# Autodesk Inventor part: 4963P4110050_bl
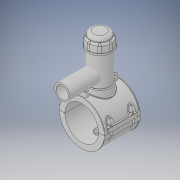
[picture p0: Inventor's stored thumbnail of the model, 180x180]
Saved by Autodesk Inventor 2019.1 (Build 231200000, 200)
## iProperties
Created: 2017-07
Part Number: 4963P4110050_bl
Material: Generic
Document SubType Name: Modeling
Designer: KIM
Density: 1 g/cm^3
Appearance: Default
Author: KIM
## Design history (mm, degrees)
derived "4963P4.ipt"
feature "Solid1::4963P4.ipt" dims "ScaleForDerivedMember" = 10
feature "Solid2::4963P4.ipt" dims "ScaleForDerivedMember" = 10
feature "Solid3::4963P4.ipt" dims "ScaleForDerivedMember" = 10
tag "TaggingFeature1"
body "Solid1"
body "Solid2"
body "Solid3"
other parameters: "d2" = 148 [user parameter], "d3" = 27.5 [user parameter], "d4" = 118 [user parameter], "d5" = 0 [user parameter], "d6" = 0.1 [user parameter], "d8" = 0 [user parameter], "d19" = 6 [user parameter], "d20" = 6 [user parameter], "d21" = 70.8 [user parameter], "d23" = 0 [user parameter], "d24" = 35.4 [user parameter], "d26" = 0 [user parameter], "d27" = 3 [user parameter], "d28" = 3 [user parameter], "d29" = 3 [user parameter], "d30" = 36.66667 [user parameter], "d31" = 6 [user parameter], "d32" = 0 [user parameter], "d33" = 0 [user parameter], "d34" = 0.6 [user parameter], "d40" = 74.36 [user parameter], "d41" = 77 [user parameter], "d43" = 0 [user parameter], "d45" = 0 [user parameter], "d47" = 142.3 [user parameter], "d70" = 15 [user parameter], "d72" = 0 [user parameter], "d73" = 6 [user parameter], "d75" = 5 [user parameter], "d76" = 0 [user parameter], "d77" = 5.5 [user parameter], "d78" = 85 [user parameter], "d79" = 15 [user parameter], "d80" = 47.2 [user parameter], "d82" = 5 deg [user parameter], "d84" = 4 [user parameter], "d85" = 14 [user parameter], "d86" = 0 [user parameter], "d87" = 3 [user parameter], "d88" = 0 [user parameter], "d89" = 1 [user parameter], "d90" = 1 [user parameter], "d91" = 94.4 [user parameter], "d92" = 0 [user parameter], "d93" = 0.5 [user parameter], "d94" = 57.89474 [user parameter], "d96" = 145.86 [user parameter], "d97" = 2.36 [user parameter], "d98" = 0 [user parameter], "d102" = 1.1 [user parameter], "d120" = 140 deg [user parameter], "d121" = 24.228 [user parameter], "d122" = 20 deg [user parameter], "d123" = 286 [user parameter], "d124" = 85.8 [user parameter], "d126" = 0 [user parameter], "d143" = 113.3 [user parameter], "d145" = 25.38462 [user parameter], "d149" = 1.65 [user parameter], "d150" = 27.92308 [user parameter], "d153" = 118 [user parameter], "d154" = 0 [user parameter], "d156" = 71.5 [user parameter], "d157" = 160 deg [user parameter], "d159" = 6.6 [user parameter], "d161" = 1.65 [user parameter], "d162" = 70.8 [user parameter], "d163" = 0 [user parameter], "d164" = 55 [user parameter], "d167" = 11 [user parameter], "d168" = 69.7561 [user parameter], "d170" = 3.75 [user parameter], "d172" = 0 [user parameter], "d173" = 1 [user parameter], "d175" = 55 [user parameter], "d176" = 20 deg [user parameter], "d177" = 7.7 [user parameter], "d178" = 33 [user parameter], "d180" = 0 [user parameter], "d183" = 13.2 [user parameter], "d184" = 6.16 [user parameter], "d185" = 38.35 [user parameter], "d186" = 38.35 [user parameter], "d187" = 71.5 [user parameter], "d188" = 9.9 [user parameter], "d189" = 7.7 [user parameter], "d190" = 0 [user parameter], "d191" = 107.25 [user parameter], "d193" = 8 [user parameter], "d194" = 4.13 [user parameter], "d195" = 90 deg [user parameter], "d197" = 0 [user parameter], "d199" = 0 [user parameter], "d200" = 16.5 [user parameter], "d202" = 0 [user parameter], "d203" = 177 [user parameter], "d204" = 73.15 [user parameter], "d205" = 53.9 [user parameter], "d206" = 65.45 [user parameter], "d207" = 132.75 [user parameter], "d208" = 138.06 [user parameter], "d209" = 164.61 [user parameter], "d210" = 66.22 [user parameter], "d211" = 77 [user parameter], "d212" = 61.6 [user parameter], "d213" = 35.1 [user parameter], "d216" = 0 [user parameter], "d217" = 11 [user parameter], "d218" = 11 [user parameter], "d219" = 2.2 [user parameter], "d224" = 0 [user parameter], "d225" = 64 [user parameter], "d228" = 123 [user parameter], "d230" = 6.6 [user parameter], "B_" = 148 [user parameter], "L_" = 118 [user parameter], "d_t" = 6 [user parameter], "H_2" = 177 [user parameter], "H_1" = 64 [user parameter], "H_" = 123 [user parameter]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
